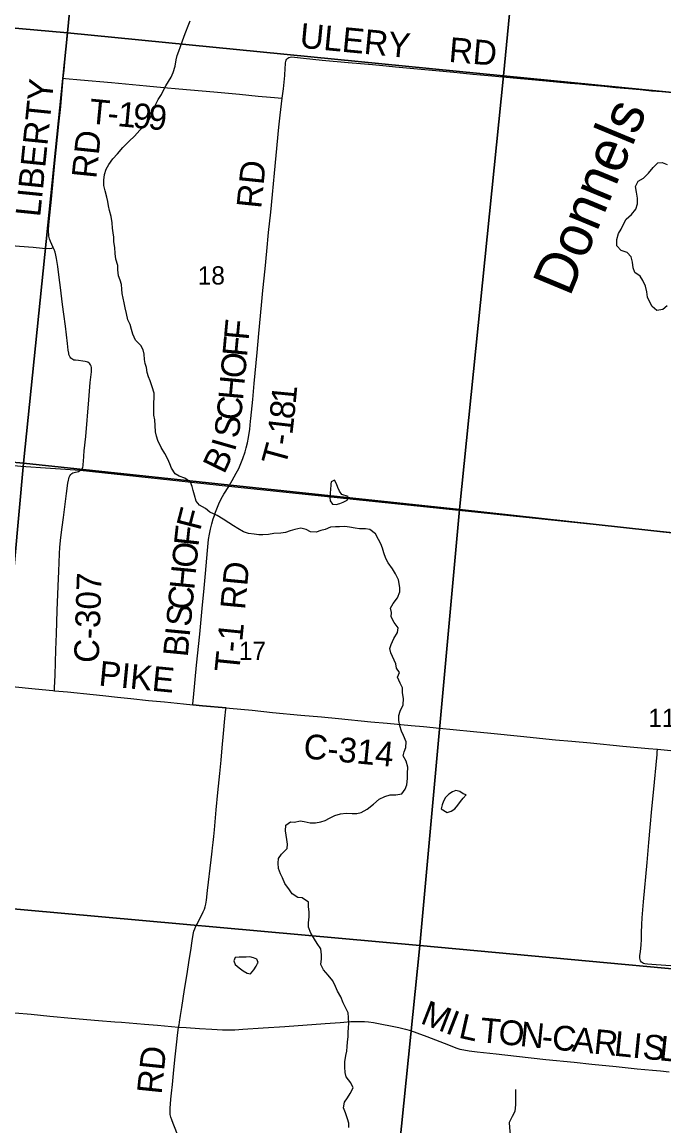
# Model space of a CAD drawing. Extents: x 0 to 1134, y 0 to 440.
# Drawn here: x 286.3 to 330.5, y 243.9 to 319.9 of the extents above; entities that cross this region are included whole.
import ezdxf

# ---------------------------------------------------------------- set-up
doc = ezdxf.new("R2010")
doc.units = 0
for name, color, linetype in [('GM_X_County_Road', 7, 'Continuous'), ('GM_X_County_Road_Text', 7, 'Continuous'), ('GM_X_Minor_Lake', 7, 'Continuous'), ('GM_X_Minor_River', 7, 'Continuous'), ('GM_X_Minor_River_Text', 7, 'Continuous'), ('GM_X_Section', 7, 'Continuous'), ('GM_X_Section_Text', 7, 'Continuous'), ('GM_X_Township', 7, 'Continuous'), ('GM_X_Township_Road', 7, 'Continuous'), ('GM_X_Township_Road_Text', 7, 'Continuous'), ('GM_X_Unincorporated', 7, 'Continuous')]:
    doc.layers.add(name, color=color, linetype=linetype)

msp = doc.modelspace()

# ---------------------------------------------------------------- linework, layer by layer
at = {"layer": 'GM_X_County_Road'}
for points in [[(289.158, 316.044), (289.206, 316.576), (289.362, 318.249), (289.433, 318.992), (289.595, 320.664)], [(288.461, 304.38), (288.278, 304.809), (288.212, 304.986), (288.186, 305.077), (288.166, 305.17), (288.152, 305.264), (288.142, 305.453), (288.143, 305.65), (288.188, 306.17), (288.352, 307.702), (288.579, 310.185), (288.856, 312.872), (288.975, 314.1), (289.054, 314.911), (289.158, 316.044)], [(290.313, 289.026), (290.354, 289.055), (290.405, 289.112), (290.467, 289.191), (290.49, 289.253), (290.512, 289.349), (290.524, 289.462), (290.535, 289.637), (290.597, 290.389), (290.699, 291.38), (290.907, 293.886), (291.011, 295.092), (291.089, 295.833), (291.097, 296.017), (291.095, 296.111), (291.072, 296.219), (291.038, 296.304), (290.987, 296.372), (290.931, 296.428), (290.852, 296.479), (290.761, 296.513), (290.665, 296.535), (290.507, 296.558), (290.196, 296.592), (289.992, 296.62), (289.885, 296.637), (289.811, 296.665), (289.738, 296.711), (289.675, 296.761), (289.625, 296.824), (289.574, 296.92), (289.546, 297.01), (289.528, 297.119), (289.501, 297.306), (289.45, 297.769), (289.296, 298.97), (289.197, 299.803), (289.11, 300.465), (288.957, 301.641), (288.867, 302.314), (288.771, 303.066), (288.692, 303.626), (288.646, 303.863), (288.59, 304.061), (288.522, 304.242), (288.461, 304.38)], [(288.546, 273.865), (288.554, 274.065), (288.59, 274.943), (288.646, 276.667), (288.686, 277.787), (288.737, 279.381), (288.81, 281.06), (288.839, 282.101), (288.884, 283.288), (288.918, 283.757), (288.991, 284.402), (289.08, 285.134), (289.164, 285.78), (289.311, 286.888), (289.382, 287.442), (289.478, 288.156), (289.51, 288.368), (289.535, 288.46), (289.568, 288.575), (289.608, 288.671), (289.664, 288.75), (289.732, 288.812), (289.811, 288.857), (289.896, 288.891), (290.196, 288.965), (290.281, 289.004), (290.313, 289.026)], [(270.079, 275.629), (272.392, 275.403), (273.969, 275.25), (275.824, 275.076), (277.216, 274.957), (279.071, 274.782), (280.184, 274.68), (281.389, 274.568), (282.409, 274.473), (283.801, 274.342), (287.231, 274.001), (288.436, 273.876), (288.546, 273.865)], [(288.546, 273.865), (289.456, 273.775), (291.217, 273.595), (291.865, 273.525), (292.885, 273.423), (293.812, 273.328), (295.015, 273.198), (296.128, 273.088), (297.425, 272.951), (298.063, 272.892)], [(298.063, 272.892), (298.724, 272.83), (300.358, 272.686)], [(300.358, 272.686), (300.581, 272.666), (302.157, 272.512), (303.547, 272.367), (305.496, 272.18), (306.917, 272.057), (308.093, 271.937), (310.319, 271.721), (311.433, 271.618), (313.099, 271.467), (313.947, 271.396), (315.047, 271.294), (315.975, 271.196), (317.368, 271.061), (318.573, 270.934), (320.613, 270.727), (323.024, 270.489), (324.137, 270.382), (325.437, 270.263), (327.663, 270.051), (329.426, 269.885), (330.042, 269.826)], [(330.042, 269.826), (333.044, 269.543), (334.436, 269.412), (335.735, 269.29), (337.405, 269.14), (339.262, 268.974), (340.839, 268.826), (341.766, 268.738), (342.787, 268.645), (343.82, 268.538), (344.929, 268.431), (345.928, 268.338), (348.256, 268.118), (349.369, 268.012), (349.613, 267.99)], [(285.826, 251.685), (286.94, 251.586), (288.238, 251.457), (289.723, 251.317), (291.58, 251.154), (292.694, 251.062), (293.156, 251.025), (294.734, 250.894), (295.648, 250.82), (297.085, 250.701)], [(297.085, 250.701), (297.598, 250.659), (298.528, 250.608), (299.364, 250.558), (300.109, 250.517), (300.576, 250.507), (300.949, 250.513), (301.508, 250.543), (302.9, 250.646), (304.387, 250.748), (307.177, 250.938), (308.199, 251.022), (308.942, 251.078), (309.313, 251.093), (309.591, 251.091), (309.868, 251.079), (310.144, 251.056), (310.509, 251.006), (310.964, 250.923), (311.781, 250.755), (312.236, 250.661), (312.688, 250.557), (313.041, 250.462), (313.476, 250.312), (314.17, 250.042), (315.648, 249.468), (316.173, 249.272), (316.441, 249.187), (316.715, 249.121), (317.084, 249.061), (317.64, 248.993), (318.937, 248.856), (320.327, 248.699), (322.365, 248.476), (324.313, 248.277), (325.518, 248.151), (327.186, 247.974), (328.649, 247.824), (329.688, 247.729), (330.241, 247.679), (330.83, 247.623)]]:
    msp.add_lwpolyline(points, dxfattribs=at)
at = {"layer": 'GM_X_Minor_Lake'}
for points in [[(308.754, 287.227), (308.323, 287.38), (308.155, 287.61), (308.044, 287.862), (307.956, 288.114), (307.811, 288.355), (307.593, 288.255), (307.567, 288.083)], [(307.567, 288.083), (307.556, 288.016), (307.53, 287.732), (307.515, 287.47), (307.489, 287.174), (307.508, 286.934), (307.688, 286.704), (307.927, 286.678), (308.19, 286.755), (308.419, 286.843), (308.683, 286.977), (308.754, 287.227)], [(316.245, 266.967), (316.166, 266.989), (315.937, 266.9), (315.673, 266.744), (315.454, 266.518), (315.314, 266.258), (315.23, 265.996), (315.147, 265.724), (315.566, 265.468)], [(315.566, 265.468), (315.84, 265.567), (316.093, 265.724), (316.29, 265.973), (316.487, 266.232), (316.672, 266.458), (316.869, 266.684), (316.665, 266.766), (316.427, 266.917), (316.245, 266.967)], [(302.526, 255.076), (302.568, 255.152), (302.468, 255.369), (302.242, 255.475), (301.992, 255.546), (301.741, 255.515), (301.49, 255.506), (301.251, 255.509), (300.988, 255.489), (300.883, 255.251)], [(300.883, 255.251), (300.982, 255.01), (301.253, 254.779), (301.535, 254.571), (301.806, 254.408), (302.034, 254.36), (302.254, 254.631), (302.428, 254.902), (302.526, 255.076)]]:
    msp.add_lwpolyline(points, dxfattribs=at)
at = {"layer": 'GM_X_Minor_River'}
for points in [[(292.288, 310.101), (292.555, 310.485), (292.89, 310.834), (293.248, 311.263), (293.687, 311.702), (294.044, 312.051), (294.414, 312.457), (294.806, 312.851), (295.108, 313.269), (295.261, 313.655), (295.379, 313.972), (295.682, 314.584), (295.914, 314.911), (296.055, 315.217), (296.218, 315.512), (296.393, 315.817), (296.567, 316.111), (296.708, 316.429), (296.85, 316.883), (296.924, 317.315), (296.985, 317.599), (297.102, 317.916), (297.209, 318.223), (297.327, 318.54), (297.468, 318.949), (297.575, 319.244), (297.739, 319.64), (297.88, 319.992)], [(330.706, 300.357), (330.395, 300.121), (329.995, 300.035), (329.68, 300.324), (329.512, 300.61), (329.357, 300.966), (329.293, 301.331), (329.218, 301.719), (329.018, 302.109), (328.84, 302.408), (328.478, 302.674), (328.368, 302.983), (328.316, 303.383), (328.229, 303.737), (327.948, 304.048), (327.54, 304.167), (327.247, 304.49), (327.242, 304.934), (327.361, 305.343), (327.535, 305.637), (327.722, 306.034), (327.886, 306.339), (328.243, 306.654), (328.544, 307.015), (328.662, 307.401), (328.667, 307.789), (328.581, 308.188), (328.529, 308.588), (328.716, 308.95), (329.072, 309.163), (329.429, 309.5), (329.73, 309.884), (330.065, 310.222), (330.35, 310.241), (330.713, 310.1)], [(309.957, 285.001), (309.535, 285.017), (309.228, 285.055), (308.842, 285.128), (308.523, 285.166), (308.158, 285.159), (307.873, 285.14), (307.542, 285.121), (307.164, 284.966), (306.879, 284.889), (306.547, 284.779), (306.16, 284.795), (305.865, 284.958), (305.502, 285.065), (305.09, 284.956), (304.77, 284.869), (304.438, 284.759), (304.119, 284.717), (303.64, 284.7), (303.274, 284.624), (302.887, 284.606), (302.602, 284.587), (302.283, 284.636), (301.908, 284.698), (301.545, 284.805), (301.171, 285.026), (300.877, 285.211), (300.55, 285.421), (300.165, 285.676), (299.747, 285.92), (299.248, 286.154), (298.933, 286.409), (298.537, 286.63), (298.301, 286.918), (298.192, 287.318), (298.093, 287.639), (298.029, 287.936), (297.918, 288.222), (297.523, 288.489), (297.138, 288.642), (296.843, 288.805), (296.597, 289.195), (296.476, 289.482), (296.354, 289.803), (296.143, 290.193), (295.897, 290.617), (295.653, 291.088), (295.565, 291.385), (295.501, 291.682), (295.472, 292.127), (295.443, 292.526), (295.378, 292.846), (295.395, 293.279), (295.389, 293.678), (295.416, 294.031), (295.397, 294.362), (295.277, 294.785), (295.134, 295.197), (295.024, 295.483), (294.925, 295.781), (294.872, 296.112), (294.796, 296.398), (294.743, 296.683), (294.724, 297.037), (294.648, 297.334), (294.493, 297.644), (294.133, 298.012), (293.932, 298.414), (293.845, 298.734), (293.747, 299.077), (293.592, 299.409), (293.494, 299.832), (293.408, 300.22), (293.344, 300.563), (293.28, 300.894), (293.215, 301.214), (293.185, 301.511), (293.166, 301.83), (293.078, 302.127), (292.945, 302.425), (292.916, 302.836), (292.897, 303.155), (292.777, 303.589), (292.714, 303.966), (292.707, 304.376), (292.632, 304.765), (292.625, 305.095), (292.583, 305.392), (292.542, 305.711), (292.512, 306.088), (292.438, 306.522), (292.329, 306.944), (292.276, 307.264), (292.223, 307.55), (292.147, 307.858), (292.038, 308.281), (291.951, 308.658), (291.945, 309.023), (291.995, 309.409), (292.102, 309.784), (292.288, 310.101)], [(306.928, 255.671), (306.865, 256.093), (306.619, 256.461), (306.429, 256.748), (306.183, 257.173), (306.029, 257.574), (306.033, 257.871), (306.072, 258.281), (306.065, 258.6), (306.025, 259.011), (306.028, 259.296), (305.588, 259.587), (305.303, 259.613), (304.896, 259.869), (304.717, 260.156), (304.404, 260.582), (304.238, 260.971), (304.105, 261.258), (303.973, 261.624), (303.932, 261.99), (303.97, 262.297), (304.179, 262.603), (304.549, 262.998), (304.575, 263.305), (304.534, 263.625), (304.492, 263.911), (304.439, 264.219), (304.455, 264.596), (304.777, 264.843), (305.073, 264.805), (305.45, 264.903), (305.735, 264.854), (306.133, 264.77), (306.508, 264.754), (306.885, 264.829), (307.172, 264.929), (307.459, 265.096), (307.837, 265.263), (308.226, 265.372), (308.614, 265.425), (309.024, 265.408), (309.354, 265.416), (309.64, 265.481), (310.064, 265.693), (310.502, 266.041), (310.883, 266.402), (311.272, 266.568), (311.65, 266.7), (312.026, 266.696), (312.448, 266.771), (312.669, 267.076), (312.787, 267.371), (312.838, 267.827), (312.842, 268.169), (312.859, 268.602), (312.739, 269.003), (312.55, 269.37), (312.599, 269.654), (312.717, 269.961), (312.756, 270.348), (312.557, 270.784), (312.435, 271.071), (312.314, 271.437), (312.239, 271.814), (312.232, 272.145), (312.339, 272.463), (312.538, 272.894), (312.555, 273.327), (312.503, 273.716), (312.484, 274.058), (312.34, 274.379), (312.14, 274.792), (312.281, 275.11), (312.091, 275.408), (312.038, 275.717), (311.683, 276.474), (311.63, 276.76), (311.702, 277.055), (311.89, 277.464), (312.146, 277.882), (312.195, 278.19), (311.926, 278.558), (311.715, 278.959), (311.73, 279.244), (311.677, 279.553), (311.852, 279.859), (312.153, 280.254), (312.306, 280.674), (312.31, 280.959), (312.214, 281.508), (312.003, 281.909), (311.802, 282.254), (311.511, 282.668), (311.344, 282.966), (311.212, 283.367), (311.125, 283.676), (310.992, 283.974), (310.836, 284.272), (310.625, 284.662), (310.253, 284.974), (309.957, 285.001)], [(308.794, 243.791), (308.797, 244.076), (308.71, 244.373), (308.567, 244.785), (308.423, 245.14), (308.497, 245.527), (308.706, 245.821), (308.903, 246.115), (309.091, 246.523), (308.947, 246.867), (308.622, 247.281), (308.557, 247.567), (308.527, 247.932), (308.532, 248.297), (308.594, 248.73), (308.655, 249.037), (308.693, 249.355), (308.72, 249.663), (308.759, 250.05), (308.763, 250.358), (308.778, 250.654), (308.805, 250.962), (308.787, 251.361), (308.757, 251.669), (308.58, 252.048), (308.413, 252.358), (308.247, 252.77), (308.024, 253.172), (307.88, 253.493), (307.703, 253.883), (307.377, 254.274), (307.051, 254.643), (306.885, 255.01), (306.913, 255.386), (306.928, 255.671)], [(315.607, 239.995), (315.931, 240.424), (316.084, 240.821), (316.122, 241.117), (316.466, 241.307), (316.912, 241.382), (317.243, 241.423), (317.551, 241.431), (317.927, 241.45), (318.235, 241.503), (318.647, 241.623), (318.969, 241.848), (319.203, 242.301), (319.618, 242.718), (319.838, 243.023), (319.922, 243.318), (319.871, 243.752), (319.864, 244.151), (320.052, 244.559), (320.25, 244.91), (320.289, 245.332), (320.294, 245.697), (320.288, 246.096), (320.28, 246.392)]]:
    msp.add_lwpolyline(points, dxfattribs=at)
at = {"layer": 'GM_X_Section'}
for points in [[(261.94, 351.945), (292.327, 348.97), (289.435, 319.16), (259.043, 321.9)], [(292.327, 348.97), (322.315, 345.859), (319.437, 316.208), (289.435, 319.16)], [(322.315, 345.859), (352.002, 343.082), (349.223, 313.27), (319.437, 316.208)], [(259.043, 321.9), (289.435, 319.16), (286.421, 289.523), (256.46, 292.203)], [(289.435, 319.16), (319.437, 316.208), (316.419, 286.332), (286.421, 289.523)], [(319.437, 316.208), (349.223, 313.27), (346.29, 283.052), (316.419, 286.332)], [(256.46, 292.203), (286.421, 289.523), (283.654, 259.029), (253.511, 261.728)], [(286.421, 289.523), (316.419, 286.332), (313.682, 256.326), (283.654, 259.029)], [(316.419, 286.332), (346.29, 283.052), (343.437, 253.571), (313.682, 256.326)], [(283.654, 259.029), (313.682, 256.326), (310.554, 225.328), (280.461, 228.248)], [(313.682, 256.326), (343.437, 253.571), (340.398, 222.479), (310.554, 225.328)]]:
    msp.add_lwpolyline(points, close=True, dxfattribs=at)
at = {"layer": 'GM_X_Township'}
msp.add_lwpolyline([(196.75, 297.507), (226.505, 294.761), (229.037, 294.531), (230.352, 294.41), (267.363, 291.111), (271.419, 290.744), (286.244, 289.327), (290.306, 289.042), (300.527, 287.945), (340.569, 283.778)], dxfattribs=at)
at = {"layer": 'GM_X_Township_Road'}
for points in [[(304.224, 314.677), (304.302, 315.31), (304.39, 316.22), (304.426, 316.732), (304.438, 317.012), (304.447, 317.105), (304.464, 317.196), (304.494, 317.285), (304.54, 317.366), (304.604, 317.433), (304.683, 317.479), (304.772, 317.502), (304.865, 317.505), (305.691, 317.426), (306.961, 317.297), (308.762, 317.124), (309.597, 317.046), (310.433, 316.976), (311.361, 316.891), (312.011, 316.833), (314.795, 316.575), (316.031, 316.462), (317.326, 316.333), (318.388, 316.239), (319.362, 316.145), (320.37, 316.057), (321.383, 315.963), (322.868, 315.81), (324.023, 315.711), (324.665, 315.651), (325.313, 315.592), (326.36, 315.493), (327.176, 315.414), (328.04, 315.33), (328.847, 315.256), (329.62, 315.18), (330.344, 315.117), (331.076, 315.053)], [(289.158, 316.044), (289.312, 316.03), (290.333, 315.937), (292.466, 315.744), (294.877, 315.521), (296.083, 315.41), (297.103, 315.316), (299.514, 315.095), (301.276, 314.937), (302.574, 314.816), (303.409, 314.741), (304.224, 314.677)], [(302.044, 292.428), (302.065, 292.607), (302.185, 293.908), (302.283, 295.023), (302.489, 297.159), (302.617, 298.459), (302.797, 300.411), (302.894, 301.432), (303.033, 302.919), (303.158, 304.125), (303.285, 305.425), (303.427, 306.817), (303.545, 308.025), (303.694, 309.511), (303.805, 310.718), (303.993, 312.669), (304.08, 313.503), (304.224, 314.677)], [(272.805, 305.596), (274.253, 305.451), (275.646, 305.332), (277.04, 305.212), (278.062, 305.124), (278.805, 305.057), (279.694, 304.988), (280.477, 304.917), (281.407, 304.849), (282.057, 304.79), (282.801, 304.737), (283.173, 304.713), (284.102, 304.643), (284.753, 304.591), (286.146, 304.485), (287.076, 304.408), (287.726, 304.346), (288.173, 304.317), (288.358, 304.344), (288.461, 304.38)], [(300.534, 287.929), (300.585, 288.01), (300.785, 288.35), (301.06, 288.838), (301.228, 289.173), (301.379, 289.516), (301.515, 289.864), (301.666, 290.306), (301.743, 290.577), (301.827, 290.942), (301.897, 291.309), (301.98, 291.864), (302.044, 292.428)], [(298.063, 272.892), (298.07, 272.969), (298.11, 273.404), (298.325, 275.632), (298.538, 277.767), (298.705, 279.531), (298.842, 280.923), (298.941, 281.944), (299.081, 283.524), (299.152, 284.265), (299.204, 284.633), (299.278, 284.997), (299.371, 285.357), (299.474, 285.703), (299.547, 285.93), (299.628, 286.167), (299.715, 286.395), (299.862, 286.735), (300.025, 287.068), (300.204, 287.393), (300.534, 287.929)], [(297.085, 250.701), (297.123, 250.861), (297.155, 251.044), (297.228, 251.505), (297.312, 252.057), (297.49, 253.274), (297.671, 254.357), (297.81, 255.312), (297.92, 255.977), (298.02, 256.631), (298.09, 257.066), (298.14, 257.296), (298.2, 257.466), (298.279, 257.64), (298.358, 257.807), (298.665, 258.381), (298.79, 258.633), (298.86, 258.808), (298.918, 258.987), (298.961, 259.17), (299.007, 259.448), (299.085, 260.096), (299.332, 262.225), (299.377, 262.597), (299.404, 262.821), (299.432, 263.051), (299.469, 263.401), (299.509, 263.826), (299.554, 264.285), (299.673, 265.664), (299.788, 266.863), (299.918, 268.162), (300.008, 269.087), (300.084, 269.919), (300.177, 270.924), (300.278, 271.938), (300.348, 272.594), (300.358, 272.686)], [(300.358, 272.686), (298.724, 272.83), (298.063, 272.892)], [(330.95, 254.914), (329.941, 254.991), (329.354, 255.031), (329.169, 255.05), (329.079, 255.074), (328.997, 255.116), (328.928, 255.178), (328.877, 255.255), (328.846, 255.342), (328.831, 255.434), (328.827, 255.526), (328.832, 255.62), (328.858, 255.884), (328.908, 256.362), (328.931, 256.733), (328.947, 257.199), (328.952, 257.757), (328.979, 258.221), (329.078, 259.334), (329.325, 262.022), (329.452, 263.413), (329.543, 264.433), (329.656, 265.731), (329.758, 266.843), (330.008, 269.474), (330.022, 269.623), (330.042, 269.826)], [(297.115, 243.079), (296.708, 244.05), (296.613, 244.313), (296.556, 244.496), (296.516, 244.676), (296.501, 244.841), (296.501, 245.14), (296.526, 245.4), (296.556, 245.73), (296.601, 246.155), (296.672, 246.754), (296.721, 247.244), (296.771, 247.763), (296.857, 248.647), (296.937, 249.482), (297.027, 250.313), (297.08, 250.679), (297.085, 250.701)]]:
    msp.add_lwpolyline(points, dxfattribs=at)
at = {"layer": 'GM_X_Unincorporated'}
msp.add_lwpolyline([(389.85, 425.107), (205.806, 425.107), (204.709, 411.927), (203.298, 395.256), (201.772, 377.614), (199.963, 356.48), (199.216, 348.073), (199.204, 347.814), (197.276, 326.922), (194.671, 297.68), (196.75, 297.507), (226.505, 294.761), (229.037, 294.531), (230.352, 294.41), (267.363, 291.111), (271.419, 290.744), (286.244, 289.327), (290.306, 289.042), (300.527, 287.945), (340.569, 283.778)], dxfattribs=at)

# ---------------------------------------------------------------- texts
at = {"layer": 'GM_X_County_Road_Text'}
for s, height, rotation, p in [('LIBERTY', 1.7045, 84.19308, (287.561, 306.448)), ('RD', 1.7045, 84.09235, (291.424, 309.088)), ('C-307', 1.7045, 88.07116, (291.592, 275.754)), ('PIKE', 1.7045, 354.44241, (291.546, 274.226)), ('C-314', 1.7045, 354.48057, (305.627, 269.213)), ('M', 1.705, 338.78436, (313.649, 250.985)), ('I', 1.705, 338.81338, (315.374, 250.315)), ('L', 1.705, 347.22208, (316.288, 249.982)), ('T', 1.705, 354.63361, (317.769, 249.662)), ('O', 1.705, 354.19444, (319.035, 249.543)), ('N', 1.705, 354.19444, (320.527, 249.392)), ('C', 1.705, 354.19426, (322.716, 249.169)), ('A', 1.705, 354.19444, (324.109, 249.027)), ('R', 1.705, 354.19717, (325.601, 248.876)), ('L', 1.705, 354.19176, (326.994, 248.734)), ('I', 1.705, 354.1951, (328.263, 248.605)), ('S', 1.705, 354.19343, (328.959, 248.534)), ('-', 1.705, 354.1951, (322.02, 249.24)), ('L', 1.705, 354.19397, (330.103, 248.418))]:
    msp.add_text(s, height=height, rotation=rotation, dxfattribs=at).set_placement(p)
at = {"layer": 'GM_X_Minor_River_Text'}
msp.add_text('Donnels', height=2.8412, rotation=67.45953, dxfattribs=at).set_placement((324.001, 300.938))
at = {"layer": 'GM_X_Section_Text'}
for s, p in [('18', (298.407, 301.836)), ('17', (301.232, 275.976)), ('11', (329.407, 271.361))]:
    msp.add_text(s, height=1.2557, rotation=0.00001, dxfattribs=at).set_placement(p)
at = {"layer": 'GM_X_Township_Road_Text'}
for s, height, rotation, p in [('ULERY', 1.7045, 354.50937, (305.373, 318.152)), ('RD', 1.7045, 355.11641, (315.636, 317.175)), ('T', 1.705, 354.49324, (290.873, 312.939)), ('1', 1.705, 354.52807, (292.84, 312.749)), ('9', 1.705, 354.64385, (293.889, 312.649)), ('9', 1.705, 355.08511, (294.948, 312.55)), ('-', 1.705, 354.49471, (292.142, 312.817)), ('RD', 1.7045, 84.13537, (302.765, 307.022)), ('F', 1.705, 84.65629, (301.9, 297.96)), ('F', 1.705, 84.65629, (301.793, 296.815)), ('O', 1.705, 84.66132, (301.653, 295.322)), ('H', 1.705, 84.65382, (301.513, 293.828)), ('1', 1.705, 84.4875, (305.138, 293.569)), ('C', 1.705, 84.39465, (301.376, 292.426)), ('8', 1.705, 84.31996, (305.034, 292.519)), ('S', 1.705, 81.44979, (301.193, 291.194)), ('1', 1.705, 83.36325, (304.909, 291.445)), ('I', 1.705, 73.95164, (300.948, 290.284)), ('-', 1.705, 81.80916, (304.803, 290.702)), ('B', 1.705, 63.94463, (300.216, 288.723)), ('T', 1.705, 74.7351, (304.421, 289.248)), ('F', 1.705, 75.43709, (298.564, 284.828)), ('F', 1.705, 83.70125, (298.45, 283.749)), ('O', 1.705, 84.45795, (298.306, 282.262)), ('H', 1.705, 84.4728, (298.161, 280.769)), ('RD', 1.7045, 84.58051, (301.652, 279.401)), ('C', 1.705, 84.47453, (298.026, 279.376)), ('S', 1.705, 84.47047, (297.916, 278.231)), ('T-1', 1.7045, 84.3018, (301.252, 275.08)), ('B', 1.705, 84.4727, (297.713, 276.141)), ('I', 1.705, 84.4773, (297.848, 277.534)), ('RD', 1.7045, 84.0934, (295.915, 246.028))]:
    msp.add_text(s, height=height, rotation=rotation, dxfattribs=at).set_placement(p)

doc.saveas('drawing.dxf')
